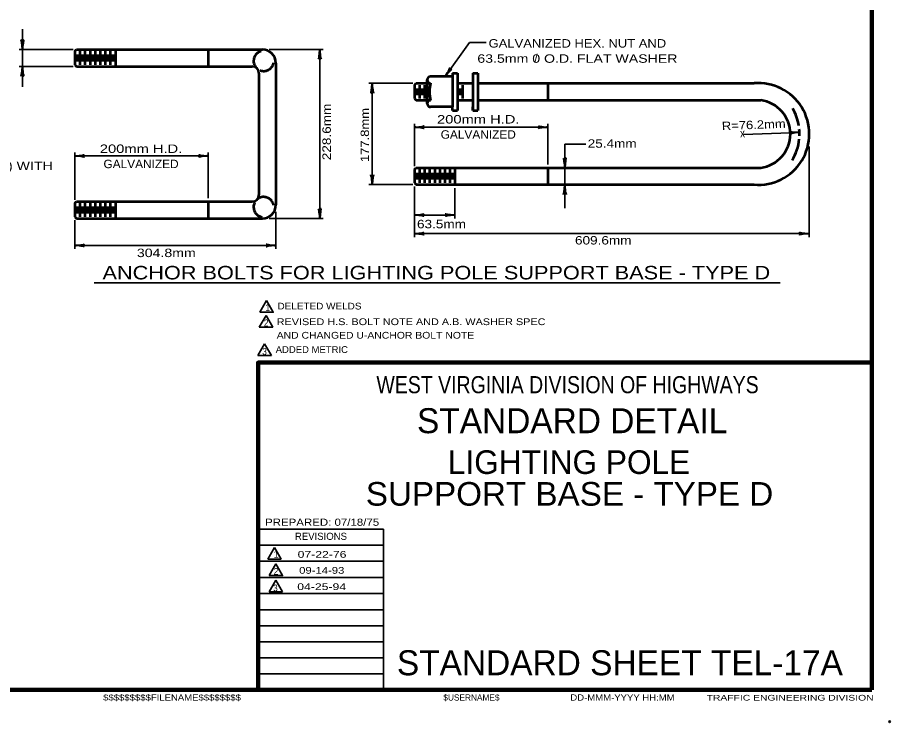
# Model space of a CAD drawing. Extents: x -35 to 821, y -23 to 522.
# Drawn here: x 511 to 821, y -22.5 to 228 of the extents above; entities that cross this region are included whole.
import ezdxf
from ezdxf.enums import TextEntityAlignment as Align

# ---------------------------------------------------------------- set-up
doc = ezdxf.new("R2010")
doc.units = 0
doc.header["$LTSCALE"] = 1.2
doc.header["$PDMODE"] = 32
doc.header["$PDSIZE"] = 0.6
doc.linetypes.add('LONG_DASHED', pattern=[7.5, 6, -1.5])
doc.layers.add('1', color=7, linetype='Continuous', lineweight=35)
doc.layers.add('61', color=7, linetype='Continuous', lineweight=35)

msp = doc.modelspace()

# ---------------------------------------------------------------- linework, layer by layer
at = {"layer": '1', "lineweight": 158}
for q in [(814.415, 515.153), (814.415, 105.353), (22.815, -10.947)]:
    msp.add_line((814.415, -10.947), q, dxfattribs=at)
at = {"layer": '1', "lineweight": 13}
msp.add_line((814.415, -10.947), (814.415, 515.153), dxfattribs=at)
at = {"layer": '1'}
for p, q in [((530.749, 216.556), (511.549, 216.556)), ((600.349, 216.556), (619.549, 216.556)), ((618.349, 216.556), (618.349, 156.556)), ((530.749, 210.556), (511.549, 210.556)), ((651.349, 204.556), (635.749, 204.556)), ((636.949, 204.556), (636.949, 168.556)), ((651.949, 175.156), (651.949, 190.156)), ((699.349, 175.756), (699.349, 190.156)), ((651.949, 188.956), (699.349, 188.956)), ((788.685, 187.134), (768.792, 186.384)), ((705.349, 174.556), (705.349, 182.956)), ((705.349, 182.956), (712.838, 182.956)), ((531.349, 163.156), (531.349, 179.956)), ((578.749, 163.756), (578.749, 179.956)), ((792.094, 182.101), (792.094, 149.956)), ((531.349, 178.756), (578.749, 178.756)), ((651.349, 168.556), (635.749, 168.556)), ((651.949, 167.956), (651.949, 149.956)), ((666.349, 167.356), (666.349, 156.556)), ((602.749, 158.956), (602.749, 145.756)), ((531.349, 155.956), (531.349, 145.756)), ((600.349, 156.556), (619.549, 156.556)), ((666.349, 157.756), (651.949, 157.756)), ((651.949, 151.156), (792.094, 151.156)), ((531.349, 146.956), (602.749, 146.956)), ((538.186, 133.674), (781.807, 133.674)), ((599.402, 127.393), (597.002, 123.236)), ((599.267, 122.113), (596.867, 117.956)), ((598.765, 111.953), (596.365, 107.797)), ((598.765, 111.953), (601.165, 107.797)), ((601.165, 107.797), (596.365, 107.797)), ((640.915, 40.453), (596.415, 40.453)), ((602.244, 39.661), (599.844, 35.504)), ((602.244, 39.661), (604.644, 35.504)), ((640.915, 34.753), (596.415, 34.753)), ((604.644, 35.504), (599.844, 35.504)), ((602.748, 33.85), (600.348, 29.694)), ((640.915, 28.953), (596.415, 28.953)), ((602.708, 28.053), (600.308, 23.896)), ((602.708, 28.053), (605.108, 23.896)), ((640.915, 23.253), (596.415, 23.253)), ((605.108, 23.896), (600.308, 23.896)), ((640.915, 17.553), (596.415, 17.553)), ((640.915, 11.853), (596.415, 11.853)), ((640.915, 6.153), (596.415, 6.153)), ((640.915, 0.453), (596.415, 0.453)), ((640.915, -5.247), (596.415, -5.247))]:
    msp.add_line(p, q, dxfattribs=at)
at = {"layer": '1', "lineweight": 53}
for p, q in [((531.349, 215.956), (531.949, 216.556)), ((531.349, 215.956), (531.349, 211.156)), ((531.949, 216.556), (597.949, 216.556)), ((532.249, 214.756), (532.249, 212.356)), ((533.149, 215.956), (533.149, 211.156)), ((534.049, 214.756), (534.049, 212.356)), ((534.949, 215.956), (534.949, 211.156)), ((535.849, 214.756), (535.849, 212.356)), ((536.749, 215.956), (536.749, 211.156)), ((537.649, 214.756), (537.649, 212.356)), ((538.549, 215.956), (538.549, 211.156)), ((539.449, 214.756), (539.449, 212.356)), ((540.349, 215.956), (540.349, 211.156)), ((541.249, 214.756), (541.249, 212.356)), ((542.149, 215.956), (542.149, 211.156)), ((543.049, 214.756), (543.049, 212.356)), ((543.949, 215.956), (543.949, 211.156)), ((544.849, 214.756), (544.849, 212.356)), ((545.749, 216.556), (545.749, 210.556)), ((578.749, 216.556), (578.749, 210.556)), ((531.349, 211.156), (531.949, 210.556)), ((602.749, 211.756), (602.749, 161.356)), ((531.949, 210.556), (594.349, 210.556)), ((596.749, 208.156), (596.749, 164.956)), ((665.449, 208.156), (667.249, 208.156)), ((665.449, 208.156), (665.449, 206.956)), ((667.249, 208.156), (667.249, 194.956)), ((672.649, 208.156), (674.449, 208.156)), ((672.649, 208.156), (672.649, 206.956)), ((674.449, 208.156), (674.449, 194.956)), ((656.449, 197.356), (656.449, 205.756)), ((656.449, 205.756), (656.449, 197.356)), ((665.449, 206.956), (657.649, 206.956)), ((665.449, 206.956), (665.449, 196.156)), ((672.649, 206.956), (672.649, 194.956)), ((651.949, 203.956), (652.549, 204.556)), ((651.949, 203.956), (651.949, 199.156)), ((652.549, 204.556), (657.649, 204.556)), ((652.849, 202.756), (652.849, 200.356)), ((653.749, 203.956), (653.749, 199.156)), ((654.649, 202.756), (654.649, 200.356)), ((655.549, 203.956), (655.549, 199.156)), ((667.249, 204.556), (672.649, 204.556)), ((667.249, 203.956), (667.249, 199.156)), ((668.149, 202.756), (668.149, 200.356)), ((669.049, 203.956), (669.049, 199.156)), ((674.449, 204.556), (772.549, 204.556)), ((699.349, 204.556), (699.349, 198.556)), ((651.949, 199.156), (652.549, 198.556)), ((652.549, 198.556), (657.649, 198.556)), ((667.249, 198.556), (672.649, 198.556)), ((674.395, 198.556), (774.949, 198.556)), ((665.449, 196.156), (657.649, 196.156)), ((665.449, 194.956), (665.449, 196.156)), ((672.649, 194.956), (672.649, 196.156)), ((665.449, 194.956), (667.249, 194.956)), ((672.649, 194.956), (674.449, 194.956)), ((651.949, 173.956), (652.549, 174.556)), ((651.949, 173.956), (651.949, 169.156)), ((652.549, 174.556), (774.949, 174.556)), ((653.749, 173.956), (653.749, 169.156)), ((655.549, 173.956), (655.549, 169.156)), ((657.349, 173.956), (657.349, 169.156)), ((659.149, 173.956), (659.149, 169.156)), ((660.949, 173.956), (660.949, 169.156)), ((662.749, 173.956), (662.749, 169.156)), ((664.549, 173.956), (664.549, 169.156)), ((666.349, 174.556), (666.349, 168.556)), ((699.349, 174.556), (699.349, 168.556)), ((652.849, 172.756), (652.849, 170.356)), ((654.649, 172.756), (654.649, 170.356)), ((656.449, 172.756), (656.449, 170.356)), ((658.249, 172.756), (658.249, 170.356)), ((660.049, 172.756), (660.049, 170.356)), ((661.849, 172.756), (661.849, 170.356)), ((663.649, 172.756), (663.649, 170.356)), ((665.449, 172.756), (665.449, 170.356)), ((651.949, 169.156), (652.549, 168.556)), ((652.549, 168.556), (772.549, 168.556)), ((531.349, 161.956), (531.949, 162.556)), ((531.349, 161.956), (531.349, 157.156)), ((531.949, 162.556), (594.349, 162.556)), ((533.149, 161.956), (533.149, 157.156)), ((534.949, 161.956), (534.949, 157.156)), ((536.749, 161.956), (536.749, 157.156)), ((538.549, 161.956), (538.549, 157.156)), ((540.349, 161.956), (540.349, 157.156)), ((542.149, 161.956), (542.149, 157.156)), ((543.949, 161.956), (543.949, 157.156)), ((545.749, 162.556), (545.749, 156.556)), ((578.749, 162.556), (578.749, 156.556)), ((532.249, 160.756), (532.249, 158.356)), ((534.049, 160.756), (534.049, 158.356)), ((535.849, 160.756), (535.849, 158.356)), ((537.649, 160.756), (537.649, 158.356)), ((539.449, 160.756), (539.449, 158.356)), ((541.249, 160.756), (541.249, 158.356)), ((543.049, 160.756), (543.049, 158.356)), ((544.849, 160.756), (544.849, 158.356)), ((531.349, 157.156), (531.949, 156.556)), ((531.949, 156.556), (597.949, 156.556))]:
    msp.add_line(p, q, dxfattribs=at)
at = {"layer": '1'}
for points in [[(512.749, 223.756), (512.749, 216.556), (512.749, 210.556), (512.749, 203.356)], [(662.848, 206.956), (671.551, 219.062), (677.42, 219.062)], [(705.349, 160.156), (705.349, 168.556), (705.349, 174.556)], [(599.402, 127.393), (601.802, 123.236), (597.002, 123.236)], [(599.267, 122.113), (601.667, 117.956), (596.867, 117.956)], [(640.915, -10.947), (640.915, 46.153), (596.415, 46.153)], [(602.748, 33.85), (605.148, 29.694), (600.348, 29.694)]]:
    msp.add_lwpolyline(points, dxfattribs=at)
at = {"layer": '1', "lineweight": 158}
msp.add_lwpolyline([(596.415, -10.947), (596.415, 105.353), (814.415, 105.353)], dxfattribs=at)
at = {"layer": '1', "linetype": 'LONG_DASHED', "lineweight": 53}
for centre, start, end in [((598.425, 212.525), 105.69018, 349.111), ((598.425, 160.583), 10.889, 261.06923)]:
    msp.add_arc(centre, 3.6, start, end, dxfattribs=at)
at = {"layer": '1', "lineweight": 53}
for centre, radius, start, end in [((597.949, 211.756), 4.8, 0, 90), ((594.349, 208.156), 2.4, 0, 90), ((657.649, 205.756), 1.2, 90, 180), ((657.649, 205.756), 1.2, 180, 270), ((774.094, 186.556), 18.066, 265.0952, 94.90479), ((669.978, 201.556), 12.688, 166.32376, 193.67624), ((657.649, 197.356), 1.2, 90, 180), ((773.344, 186.556), 12.107, 277.62006, 82.37994), ((657.649, 197.356), 1.2, 180, 270), ((770.628, 186.556), 18.066, 9.37052, 30.07893), ((770.628, 186.556), 18.066, 357.92796, 5.54536), ((770.628, 186.556), 18.066, 328.90929, 354.10244), ((594.349, 164.956), 2.4, 270, 0), ((597.949, 161.356), 4.8, 270, 0)]:
    msp.add_arc(centre, radius, start, end, dxfattribs=at)
at = {"layer": '1', "lineweight": 40}
for centre, major_axis, ratio, start_param, end_param in [((512.418, 217.865), (0.187, -2.143), 0.122415, 0.8963533, 3.1415927), ((512.418, 217.865), (0.187, -2.143), 0.122415, 0.8963533, 3.1415927), ((513.003, 217.901), (-0.211, -2.108), 0.07063, 3.1407148, 5.41811), ((513.003, 217.901), (-0.211, -2.108), 0.07063, 3.1407148, 5.41811), ((618.095, 215.211), (0.211, 2.108), 0.07063, 3.1407148, 5.41811), ((618.095, 215.211), (0.211, 2.108), 0.07063, 3.1407148, 5.41811), ((618.681, 215.247), (-0.187, 2.143), 0.122415, 0.8963533, 3.1415927), ((618.681, 215.247), (-0.187, 2.143), 0.122415, 0.8963533, 3.1415927), ((512.495, 209.211), (0.211, 2.108), 0.07063, 3.1407148, 5.41811), ((512.495, 209.211), (0.211, 2.108), 0.07063, 3.1407148, 5.41811), ((513.081, 209.247), (-0.187, 2.143), 0.122415, 0.8963533, 3.1415927), ((513.081, 209.247), (-0.187, 2.143), 0.122415, 0.8963533, 3.1415927), ((663.343, 208.213), (-1.099, -1.849), 0.122415, 0.8963533, 3.1415927), ((663.839, 207.9), (1.401, 1.588), 0.07063, 6.2823074, 8.5597026), ((636.695, 203.211), (0.211, 2.108), 0.07063, 3.1407148, 5.41811), ((636.695, 203.211), (0.211, 2.108), 0.07063, 3.1407148, 5.41811), ((637.281, 203.247), (-0.187, 2.143), 0.122415, 0.8963533, 3.1415927), ((637.281, 203.247), (-0.187, 2.143), 0.122415, 0.8963533, 3.1415927), ((653.259, 189.288), (-2.143, -0.187), 0.122415, 0.8963533, 3.1415927), ((653.259, 189.288), (-2.143, -0.187), 0.122415, 0.8963533, 3.1415927), ((698.005, 189.21), (2.108, -0.211), 0.07063, 3.1407148, 5.41811), ((653.294, 188.702), (-2.108, 0.211), 0.07063, 3.1407148, 5.41811), ((653.294, 188.702), (-2.108, 0.211), 0.07063, 3.1407148, 5.41811), ((698.04, 188.624), (2.143, 0.187), 0.122415, 0.8963533, 3.1415927), ((787.332, 187.337), (2.114, -0.131), 0.07063, 3.1407148, 5.41811), ((787.389, 186.753), (2.134, 0.268), 0.122415, 0.8963533, 3.1415927), ((532.694, 178.502), (-2.108, 0.211), 0.07063, 3.1407148, 5.41811), ((532.694, 178.502), (-2.108, 0.211), 0.07063, 3.1407148, 5.41811), ((532.659, 179.088), (-2.143, -0.187), 0.122415, 0.8963533, 3.1415927), ((532.659, 179.088), (-2.143, -0.187), 0.122415, 0.8963533, 3.1415927), ((577.44, 178.424), (2.143, 0.187), 0.122415, 0.8963533, 3.1415927), ((577.405, 179.01), (2.108, -0.211), 0.07063, 3.1407148, 5.41811), ((705.018, 175.865), (0.187, -2.143), 0.122415, 0.8963533, 3.1415927), ((705.018, 175.865), (0.187, -2.143), 0.122415, 0.8963533, 3.1415927), ((705.603, 175.901), (-0.211, -2.108), 0.07063, 3.1407148, 5.41811), ((705.603, 175.901), (-0.211, -2.108), 0.07063, 3.1407148, 5.41811), ((636.618, 169.865), (0.187, -2.143), 0.122415, 0.8963533, 3.1415927), ((637.203, 169.901), (-0.211, -2.108), 0.07063, 3.1407148, 5.41811), ((705.095, 167.211), (0.211, 2.108), 0.07063, 3.1407148, 5.41811), ((705.681, 167.247), (-0.187, 2.143), 0.122415, 0.8963533, 3.1415927), ((618.018, 157.865), (0.187, -2.143), 0.122415, 0.8963533, 3.1415927), ((618.018, 157.865), (0.187, -2.143), 0.122415, 0.8963533, 3.1415927), ((618.603, 157.901), (-0.211, -2.108), 0.07063, 3.1407148, 5.41811), ((618.603, 157.901), (-0.211, -2.108), 0.07063, 3.1407148, 5.41811), ((653.259, 158.088), (-2.143, -0.187), 0.122415, 0.8963533, 3.1415927), ((653.259, 158.088), (-2.143, -0.187), 0.122415, 0.8963533, 3.1415927), ((665.005, 158.01), (2.108, -0.211), 0.07063, 3.1407148, 5.41811), ((653.294, 157.502), (-2.108, 0.211), 0.07063, 3.1407148, 5.41811), ((653.294, 157.502), (-2.108, 0.211), 0.07063, 3.1407148, 5.41811), ((665.04, 157.424), (2.143, 0.187), 0.122415, 0.8963533, 3.1415927), ((653.294, 150.902), (-2.108, 0.211), 0.07063, 3.1407148, 5.41811), ((653.294, 150.902), (-2.108, 0.211), 0.07063, 3.1407148, 5.41811), ((653.259, 151.488), (-2.143, -0.187), 0.122415, 0.8963533, 3.1415927), ((653.259, 151.488), (-2.143, -0.187), 0.122415, 0.8963533, 3.1415927), ((790.784, 150.824), (2.143, 0.187), 0.122415, 0.8963533, 3.1415927), ((790.749, 151.41), (2.108, -0.211), 0.07063, 3.1407148, 5.41811), ((532.694, 146.702), (-2.108, 0.211), 0.07063, 3.1407148, 5.41811), ((532.694, 146.702), (-2.108, 0.211), 0.07063, 3.1407148, 5.41811), ((532.659, 147.288), (-2.143, -0.187), 0.122415, 0.8963533, 3.1415927), ((532.659, 147.288), (-2.143, -0.187), 0.122415, 0.8963533, 3.1415927), ((601.44, 146.624), (2.143, 0.187), 0.122415, 0.8963533, 3.1415927), ((601.405, 147.21), (2.108, -0.211), 0.07063, 3.1407148, 5.41811)]:
    msp.add_ellipse(centre, major_axis=major_axis, ratio=ratio, start_param=start_param, end_param=end_param, dxfattribs=at)
at = {"layer": '1'}
msp.add_point((820.715, -22.247), dxfattribs=at)
at = {"layer": '61', "lineweight": 53}
for q in [(661.715, -10.947), (661.715, -10.947), (661.715, -10.947), (662.015, -10.947), (662.015, -10.947)]:
    msp.add_line((814.415, -10.947), q, dxfattribs=at)

# ---------------------------------------------------------------- texts
at = {"layer": '1'}
for s, height, width, p in [('GALVANIZED HEX. NUT AND', 3, 1.15, (709.813, 217.252)), ('63.5mm 0 O.D. FLAT WASHER', 3, 1.25, (709.813, 211.852)), ('200mm H.D.', 3, 1.3, (674.618, 190.278)), ('GALVANIZED', 3, 1.05, (674.618, 184.878)), ('200mm H.D.', 3, 1.3, (554.875, 179.819)), ('25mm 0 METAL CONDUIT (TYP.) WITH', 3, 1.25, (478.224, 173.743)), ('GALVANIZED', 3, 1.05, (554.875, 174.419)), ('WEST VIRGINIA DIVISION OF HIGHWAYS', 6.089, 0.85, (706.315, 94.453)), ('SUPPORT BASE - TYPE D', 8.391, 1.05, (707.031, 54.507)), ('07-22-76', 2.4, 1.35, (619.145, 35.988)), ('09-14-93', 2.4, 1.25, (619.042, 30.311)), ('04-25-94', 2.4, 1.35, (619.012, 24.514))]:
    msp.add_text(s, height=height, dxfattribs=dict(at, width=width)).set_placement(p, align=Align.CENTER)
for s, height, p in [('/', 3, (694.545, 211.878)), ('1', 2.4, (598.97, 123.693)), ('REVISIONS', 2.537, (609.515, 42.353)), ('1', 2.4, (601.945, 36.025)), ('STANDARD SHEET TEL-17A', 8.881, (645.715, -5.747)), ('$USERNAME$', 2.2, (662.215, -14.747))]:
    msp.add_text(s, height=height, dxfattribs=at).set_placement(p)
for s, rotation, width, p in [('228.6mm', 90, 1.2, (622.264, 177.244)), ('177.8mm', 90, 1.15, (635.831, 176.572)), ('R=76.2mm', 2.158, 1.15, (761.157, 187.903)), ('x', 2.158, 0.85, (767.638, 185.329))]:
    msp.add_text(s, height=3, rotation=rotation, dxfattribs=dict(at, width=width)).set_placement(p)
for s, height, width, p in [('25.4mm', 3, 1.2, (713.471, 181.67)), ('63.5mm', 3, 1.2, (652.866, 153.059)), ('609.6mm', 3, 1.2, (708.966, 147.288)), ('304.8mm', 3, 1.25, (553.393, 142.82)), ('ANCHOR BOLTS FOR LIGHTING POLE SUPPORT BASE - TYPE D', 4.8, 1.2, (541.18, 134.889)), ('DELETED WELDS', 2.4, 1.1, (603.323, 124.205)), ('REVISED H.S. BOLT NOTE AND A.B. WASHER SPEC', 2.4, 1.2, (603.045, 118.649)), ('2', 2.4, 0.9, (598.509, 118.25)), ('AND CHANGED U-ANCHOR BOLT NOTE', 2.4, 1.15, (603.045, 113.849)), ('3', 2.4, 0.9, (597.936, 108.094)), ('ADDED METRIC', 2.4, 1.05, (602.686, 108.766)), ('PREPARED: 07/18/75', 2.537, 1.2, (598.915, 47.353)), ('2', 2.4, 0.9, (601.99, 29.987)), ('3', 2.4, 0.9, (601.791, 24.071)), ('$$$$$$$$$FILENAME$$$$$$$$', 2.2, 1.15, (541.415, -14.747)), ('DD-MMM-YYYY HH:MM', 2.2, 1.15, (707.315, -14.747)), ('TRAFFIC ENGINEERING DIVISION', 2.031, 1.35, (755.715, -14.747))]:
    msp.add_text(s, height=height, dxfattribs=dict(at, width=width)).set_placement(p)
for s, height, p in [('STANDARD DETAIL', 8.881, (707.965, 80.253)), ('LIGHTING POLE', 8.391, (706.847, 65.774))]:
    msp.add_text(s, height=height, dxfattribs=at).set_placement(p, align=Align.CENTER)

doc.saveas('drawing.dxf')
